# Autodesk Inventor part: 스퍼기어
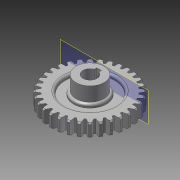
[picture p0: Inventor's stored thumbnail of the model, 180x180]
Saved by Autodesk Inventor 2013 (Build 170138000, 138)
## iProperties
Created: 2010-04
Part Number: 스퍼기어
Material: 강
Document SubType Name: Modeling
Designer: KYOUNG IL JANG
Categories: <?xml version="1.0" encoding="UTF-16"?> <MemberInstance><Categories><FamilyTemplate><FamilyTemplateParameter ValueType="xs:double" Id="1" ObjectReferenceKey="da
Density: 7.85 g/cm^3
Mass: 256.791 g
Surface Area: 133.154 cm^2
Volume: 32.7122 cm^3
CustomPartVersion: 1
Author: 진현석
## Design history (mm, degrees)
sketch "Sketch1"
  geometry: C1 r 34 at (0, 0)
  constraints: 1 centre point
  dimensions: "d0" = 68 diameter of C1 (= da_da)
extrude "Extrusion1" new body sketch "Sketch1" distance "d1" = 11 (= da_b); taper "d2" = 0 deg
chamfer "모따기2" distance "d62" = 1; stored, may be unused: second distance "d63" = 2, angle "d64" = 45 deg
workplane "Work Plane2"
feature "피치 지름" dims "d4" = 10, "d5" = 0
workplane "Work Plane8"
workplane "Work Plane9"
feature "스퍼 기어" dims "da_b" = 11, "da_d" = 64, "da_aw" = 96, "da_da" = 68, "da_df" = 59, "da_dw" = 64, angle "da_beta" = 0 deg, "da_lefttooth" = 0, "da_righttooth" = 0
sketch "스케치5"
  geometry: L1 (-2, 5.657)-(2, 5.657); L2 (2, 5.657)-(2, 7.8); L3 (2, 7.8)-(-2, 7.8); L4 (-2, 7.8)-(-2, 5.657); A1 r 6 centre (0, 0) between (-2, 5.657) and (2, 5.657); 1 further point
  constraints: 8 end point, 2 parallel, 2 point on circle, 1 centre point, 1 coincident, 1 horizontal, 1 perpendicular
  dimensions: "d65" = 12 diameter of A1; "d66" = 4 distance of L2.end L3.end; "d67" = 13.8 dimension on A1 L3
extrude "돌출4" cut sketch "스케치5" stored distance "d68" = 10; taper "d69" = 0 deg
sketch "스케치6"
  geometry: L1 (7.8, 0)-(7.8, 11) reference; L2 (7.8, 11)-(33, 11) reference; L3 (33, 11)-(34, 10) reference; L4 (34, 10)-(34, 1) reference; L5 (34, 1)-(33, 0) reference; L6 (33, 0)-(7.8, 0) reference; L7 (-6, 11)-(-6, 0) reference; L8 (-6, 0)-(-33, 0) reference; L9 (-33, 0)-(-34, 1) reference; L10 (-34, 1)-(-34, 10) reference; L11 (-34, 10)-(-33, 11) reference; L12 (-33, 11)-(-6, 11) reference; L13 (-21, 11)-(-14, 11); L14 (-14, 11)-(-14, 8); L15 (-14, 8)-(-21, 8); L16 (-21, 8)-(-21, 11); L17 (-21, 0)-(-14, 0); L18 (-14, 0)-(-14, 3); L19 (-14, 3)-(-21, 3); L20 (-21, 3)-(-21, 0); L21 (0, -2.202)-(0, 13.202) reference; 1 further point
  constraints: 16 end point, 4 parallel, 2 equal length, 2 horizontal, 2 perpendicular, 2 point on line, 1 collinear
  dimensions: "d70" = 3 distance of L13.end L14.end; "d71" = 28 diameter of L14 L21; "d72" = 42 diameter of L16 L21
revolve "회전1" sketch "스케치6" stored, may be unused: angle "d73" = 90 deg
fillet "모깎기2" dims "d74" = 2
sketch "스케치7"
  geometry: L1 (-2, 5.657)-(-2, 7.8) reference; L2 (-2, 7.8)-(2, 7.8) reference; L3 (2, 7.8)-(2, 5.657) reference; C1 r 12 at (0, 0) reference; A1 r 6 centre (0, 0) between (-2, 5.657) and (2, 5.657) reference
extrude "돌출5" join sketch "스케치7" distance "d75" = 12; taper "d76" = 0 deg
node "작업 평면12"
sketch "스케치8"
  geometry: L1 (12, 12)-(-12, 12) reference; 2 further points
  constraints: 1 vertical alignment
  dimensions: "d77" = 6 distance from line of point (0, 6) L1
hole "구멍1" sketch "스케치8" at (0, 6) diameter "d78" = 2.459; stored, may be unused: countersink angle "d82" = 90 deg, drill point angle "d84" = 118 deg; dims "d79" = 6, "d80" = 4, "d81" = 2, "d83" = 8
body "Solid1"
sketch "Sketch2"
  geometry: C1 r 34 at (0, 0) reference; C2 r 32 at (0, 0)
  constraints: 1 centre point, 1 coincident
  dimensions: "d3" = 64 diameter of C2 (= da_dw)
body "Srf1"
node "투영된 루프1"
node "절단 모서리 투영1"
other parameters: "d16" = 96 (= da_aw), "d17" = 0, "d34" = 0.98175 (computed from da_z), "d39" = 0, "d41" = 0, "d43" = 96 (= da_aw), "d46" = 96 (= da_aw), "d47" = 0, "d48" = 0
